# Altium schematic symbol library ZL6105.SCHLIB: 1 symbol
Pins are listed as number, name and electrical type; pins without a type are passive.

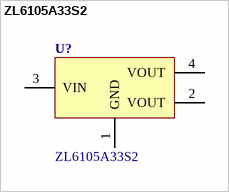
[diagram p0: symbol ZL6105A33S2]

## ZL6105A33S2
designator U?
物料代码: 89.12.00022; 名称: 集成电路; 封装: SOT-223; 厂商: ZHIYUAN; 贴片和直插: SMT; PCB备注: 200102ZW; 器件优选方案: 待导入物料
footprint SOT229P700X180-4N
pins: 1 GND, 2 VOUT, 3 VIN, 4 VOUT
